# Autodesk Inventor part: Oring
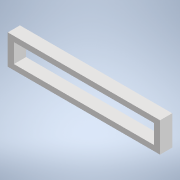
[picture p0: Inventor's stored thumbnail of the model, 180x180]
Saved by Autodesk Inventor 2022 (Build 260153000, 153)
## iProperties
Created: 2022-05
Part Number: Oring
Material: Generic
Document SubType Name: Modeling
Designer: valen
Density: 1 g/cm^3
Appearance: Default
Author: valen
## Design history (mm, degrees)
sketch "Sketch1"
  geometry: L1 (-33.5, -43.5)-(-33.5, -46) reference; L2 (-13.5, -46)-(-33.5, -46) reference; L3 (-13.5, -43.5)-(-13.5, -46) reference; L4 (-33.5, -43.5)-(-13.5, -43.5) reference; L5 (-14.3, -43.5)-(-14.3, -46) reference; L6 (-32.7, -43.5)-(-32.7, -46) reference; L7 (-32.7, -46)-(-14.3, -43.5); L8 (-13.5, -46.703)-(-33.5, -46.703); L9 (-33.5, -46.703)-(-33.5, -42.797); L10 (-33.5, -42.797)-(-13.5, -42.797); L11 (-13.5, -42.797)-(-13.5, -46.703); L12 (-13.5, -46.703)-(-33.5, -42.797); L13 (-33.5, -46.703)-(-13.5, -42.797); 6 further points
  constraints: 18 end point, 3 midpoint, 2 parallel, 2 vertical, 1 horizontal, 1 perpendicular, 4 other
extrude "Extrusion1" new body sketch "Sketch1" distance "d0" = 1.6; taper "d1" = 0 deg
fillet "Fillet1" dims "d2" = 0.3
body "Solid1"
node "Reference1"
